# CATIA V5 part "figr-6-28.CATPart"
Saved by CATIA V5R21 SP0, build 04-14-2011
Part number: Part1
Bounding box of the stored display mesh (mm): x -150 to 0, y -70 to 60, z -20 to 40
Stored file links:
  D:\CATIAV5R21-WORK\c06_cat_v5r21\catia-files\FIGURE-6-28.CATPart
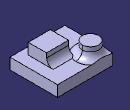
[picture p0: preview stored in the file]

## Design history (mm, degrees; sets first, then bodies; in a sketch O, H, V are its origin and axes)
Body1 (main body)
  Sketch1 on yz-plane, origin (0, 0, 0), H (0, 1, 0), V (0, 0, 1)
    line L1 (-70, 10) -> (60, 10)
    line L2 (60, 10) -> (60, -20)
    line L3 (60, -20) -> (-70, -20)
    line L4 (-70, -20) -> (-70, 10)
    horizontal: L1 H, L3 H
    vertical: L2 V, L4 V
  Pad1: profile Sketch1, direction (-1, 0, 0), length 150
  Sketch2 on face of Pad1 from Sketch1.L1, origin (0, 0, 10), H (1, 0, 0), V (0, 1, 0)
    circle A1 centre (-120, 30) radius 22.3607
  Pad2: profile Sketch2, direction (0, 0, 1), length 30
  Sketch3 on face of Pad1 from Sketch1.L1, origin (0, 0, 10), H (1, 0, 0), V (0, 1, 0)
    point P1 (-90, 0)
    line L1 (-90, 0) -> (-30, 0)
    line L2 (-30, 0) -> (-30, -50)
    line L3 (-30, -50) -> (-90, -50)
    line L4 (-90, -50) -> (-90, 0)
    coincidence: P1 H
    horizontal: L1 H, L3 H
    vertical: L2 V, L4 V
  Pad3: profile Sketch3, direction (0, 0, 1), length 30
  Fillet1: radius 18, on edge [face of Pad1 from Sketch1.L1 | face of Pad3 from Sketch3.L1]; edge [face of Pad1 from Sketch1.L1 | face of Pad2 from Sketch2.A1]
